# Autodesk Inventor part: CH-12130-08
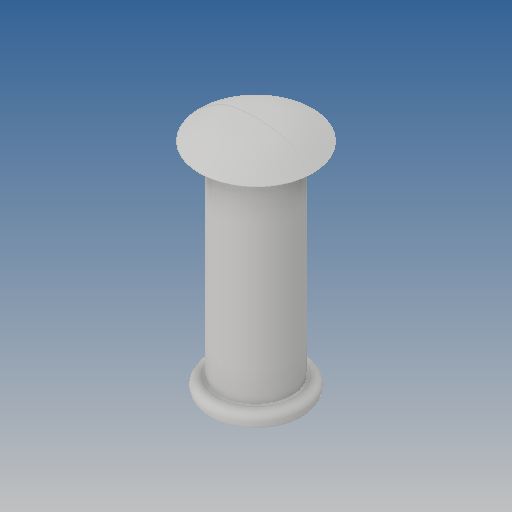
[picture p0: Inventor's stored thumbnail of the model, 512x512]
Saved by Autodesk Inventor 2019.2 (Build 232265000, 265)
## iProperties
Created: 2012-09
Part Number: CH-12130-08
Material: Ogólny
Document SubType Name: Modeling
Designer: CADENGINEERING4
Density: 1 g/cm^3
Appearance: Domyślna
Author: CADENGINEERING4
Revision Number: ÈÎºÎ
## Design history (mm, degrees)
feature "Ô²½Ç2"
node "Bryła1"
